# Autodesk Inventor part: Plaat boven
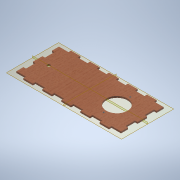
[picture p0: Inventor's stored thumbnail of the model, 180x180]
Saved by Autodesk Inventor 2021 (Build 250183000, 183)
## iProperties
Manager: PJ / DCS
Company: Emmaüs Bovenbouw Aalter
Created: 2021-01
Part Number: Plaat boven
Material: S235
Catalog Web Link: http://emmausbovenbouw.op-weg.be/
Vendor: Emmaüsinstituut Bovenbouw Aalter
Document SubType Name: Modeling
Designer: Antho
Engineer: Declercq St.
Manufacturer: Standard
Standards Organization: Custom
Density: 7.86 g/cm^3
Appearance: Steel
Title: Algemene titel
Subject: Specifieke titel
Author: Antho
Keywords: Ruwe Ø xxxxx
Comments: Opmerking
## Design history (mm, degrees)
sketch "Sketch1"
  geometry: L1 (0, 2.858)-(0, -2.858); L2 (-5.777, 0)-(5.777, 0); L3 (-165, -75)-(165, -75); L4 (165, -75)-(165, 75); L5 (165, 75)-(-165, 75); L6 (-165, 75)-(-165, -75); L7 (-165, -75)-(165, 75); L8 (165, -75)-(-165, 75); 2 further points
  constraints: 16 end point, 4 midpoint, 2 horizontal, 2 parallel, 1 coincident, 1 perpendicular, 1 vertical
  dimensions: "d0" = 330 distance of L5.end L4.end; "d1" = 150 distance of L4.end L3.end
extrude "Extrusion1" new body sketch "Sketch1" distance "d2" = 5; taper "d3" = 0 deg
sketch "Sketch2"
  geometry: L1 (0, 0)-(-130, 0); L2 (-165, 75)-(-165, -75) reference; L3 (-165, 0)-(-165, 15); L4 (-165, 15)-(-165, -15); L5 (-165, -15)-(-165, -45); L6 (-165, -45)-(-165, -75); L7 (-165, 15)-(-165, 45); L8 (-165, 45)-(-165, 75); L9 (-165, 15)-(-157, 15); L10 (-157, 15)-(-157, 45); L11 (-157, 45)-(-165, 45); L12 (-165, 45)-(-165, 15); L13 (-165, -15)-(-157, -15); L14 (-157, -15)-(-157, -45); L15 (-157, -45)-(-165, -45); L16 (-165, -45)-(-165, -15); L17 (-165, -75)-(-135, -75); L18 (-135, -75)-(-105, -75); L19 (-105, -75)-(-75, -75); L20 (-75, -75)-(-45, -75); L21 (-45, -75)-(-15, -75); L22 (-15, -75)-(15, -75); L23 (15, -75)-(45, -75); L24 (45, -75)-(75, -75); L25 (75, -75)-(105, -75); L26 (105, -75)-(135, -75); L27 (135, -75)-(165, -75); L28 (-165, -75)-(-135, -75); L29 (-135, -75)-(-135, -67); L30 (-135, -67)-(-165, -67); L31 (-165, -67)-(-165, -75); L32 (-105, -75)-(-75, -75); L33 (-75, -75)-(-75, -67); L34 (-75, -67)-(-105, -67); L35 (-105, -67)-(-105, -75); L36 (-45, -75)-(-15, -75); L37 (-15, -75)-(-15, -67); L38 (-15, -67)-(-45, -67); L39 (-45, -67)-(-45, -75); L40 (15, -75)-(45, -75); L41 (45, -75)-(45, -67); L42 (45, -67)-(15, -67); L43 (15, -67)-(15, -75); L44 (75, -75)-(105, -75); L45 (105, -75)-(105, -67); L46 (105, -67)-(75, -67); L47 (75, -67)-(75, -75); L48 (135, -75)-(165, -75); L49 (165, -75)-(165, -67); L50 (165, -67)-(135, -67); L51 (135, -67)-(135, -75); L52 (165, 75)-(-165, 75) reference; L53 (-165, 75)-(-135, 75); L54 (-135, 75)-(-135, 67); L55 (-135, 67)-(-165, 67); L56 (-165, 67)-(-165, 75); L57 (-105, 75)-(-75, 75); L58 (-75, 75)-(-75, 67); L59 (-75, 67)-(-105, 67); L60 (-105, 67)-(-105, 75); L61 (-45, 75)-(-15, 75); L62 (-15, 75)-(-15, 67); L63 (-15, 67)-(-45, 67); L64 (-45, 67)-(-45, 75)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; C1 r 5 at (-130, 0); 22 further points
  constraints: 166 end point, 35 point on line, 32 parallel, 17 horizontal, 16 perpendicular, 2 collinear, 2 midpoint, 1 centre point, 1 coincident, 11 other
  dimensions: "d4" = 130 distance of L1.start L1.end; "d5" = 10 diameter of C1; "d6" = 15 distance of L3.start L3.end; "d7" = 30 distance of L3.end L4.end; "d8" = 30 distance of L4.end L5.end; "d9" = 30 distance of L5.end L2.end (derived); "d10" = 30 distance of L3.end L7.end; "d11" = 30 distance of L7.end L2.start (derived); "d12" = 8 distance of L11.end L10.end; "d13" = 30 distance of L2.end L17.end; "d14" = 30 distance of L17.end L18.end; "d15" = 30 distance of L18.end L19.end; "d16" = 30 distance of L19.end L20.end; "d17" = 30 distance of L20.end L21.end; "d18" = 30 distance of L21.end L22.end; "d19" = 30 distance of L22.end L23.end; "d20" = 30 distance of L23.end L24.end; "d21" = 30 distance of L24.end L25.end; "d22" = 30 distance of L25.end L26.end; "d23" = 30 distance of L26.end L27.end; "d24" = 8 distance of L29.end L28.end; "d25" = 8 distance of L53.end L54.end; "d26" = 8 distance of L80.end L81.end; "d29" = 30 distance of L29.end L30.end; "d30" = 30 distance of L33.end L34.end; "d31" = 30 distance of L37.end L38.end; "d32" = 30 distance of L41.end L42.end; "d33" = 30 distance of L45.end L46.end; "d34" = 30 distance of L49.end L50.end
extrude "Extrusion2" cut sketch "Sketch2" distance "d27" = 8; taper "d28" = 0 deg
sketch "Sketch3"
  geometry: L1 (165, -15)-(165, 15) reference; L2 (165, 0)-(85, 0); C1 r 33.5 at (85, 0); 1 further point
  constraints: 2 end point, 1 centre point, 1 coincident, 1 horizontal, 1 midpoint
  dimensions: "d35" = 80 distance of L2.start L2.end; "d36" = 67 diameter of C1
extrude "Extrusion3" cut sketch "Sketch3" distance "d37" = 10; taper "d38" = 0 deg
sketch "Sketch4"
  geometry: L1 (85, 0)-(85, 42); L2 (85, 0)-(85, -42); C1 r 33.5 at (85, 0) reference; C2 r 2.5 at (85, 42); C3 r 2.5 at (85, -42); 1 further point
  constraints: 4 end point, 2 centre point, 2 coincident, 2 vertical
  dimensions: "d39" = 42 distance of L1.start L1.end; "d40" = 5 diameter of C2; "d41" = 42 distance of L1.start L2.end; "d42" = 5 diameter of C3
extrude "Extrusion4" cut sketch "Sketch4" distance "d43" = 5; taper "d44" = 0 deg
body "Solid1"
